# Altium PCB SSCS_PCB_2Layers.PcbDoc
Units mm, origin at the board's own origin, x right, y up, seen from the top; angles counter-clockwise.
Board outline 50.93 x 54.61 mm, 2 copper layers (Top Layer, Bottom Layer); 15 components, 35 nets, 400 pads, 22 vias.
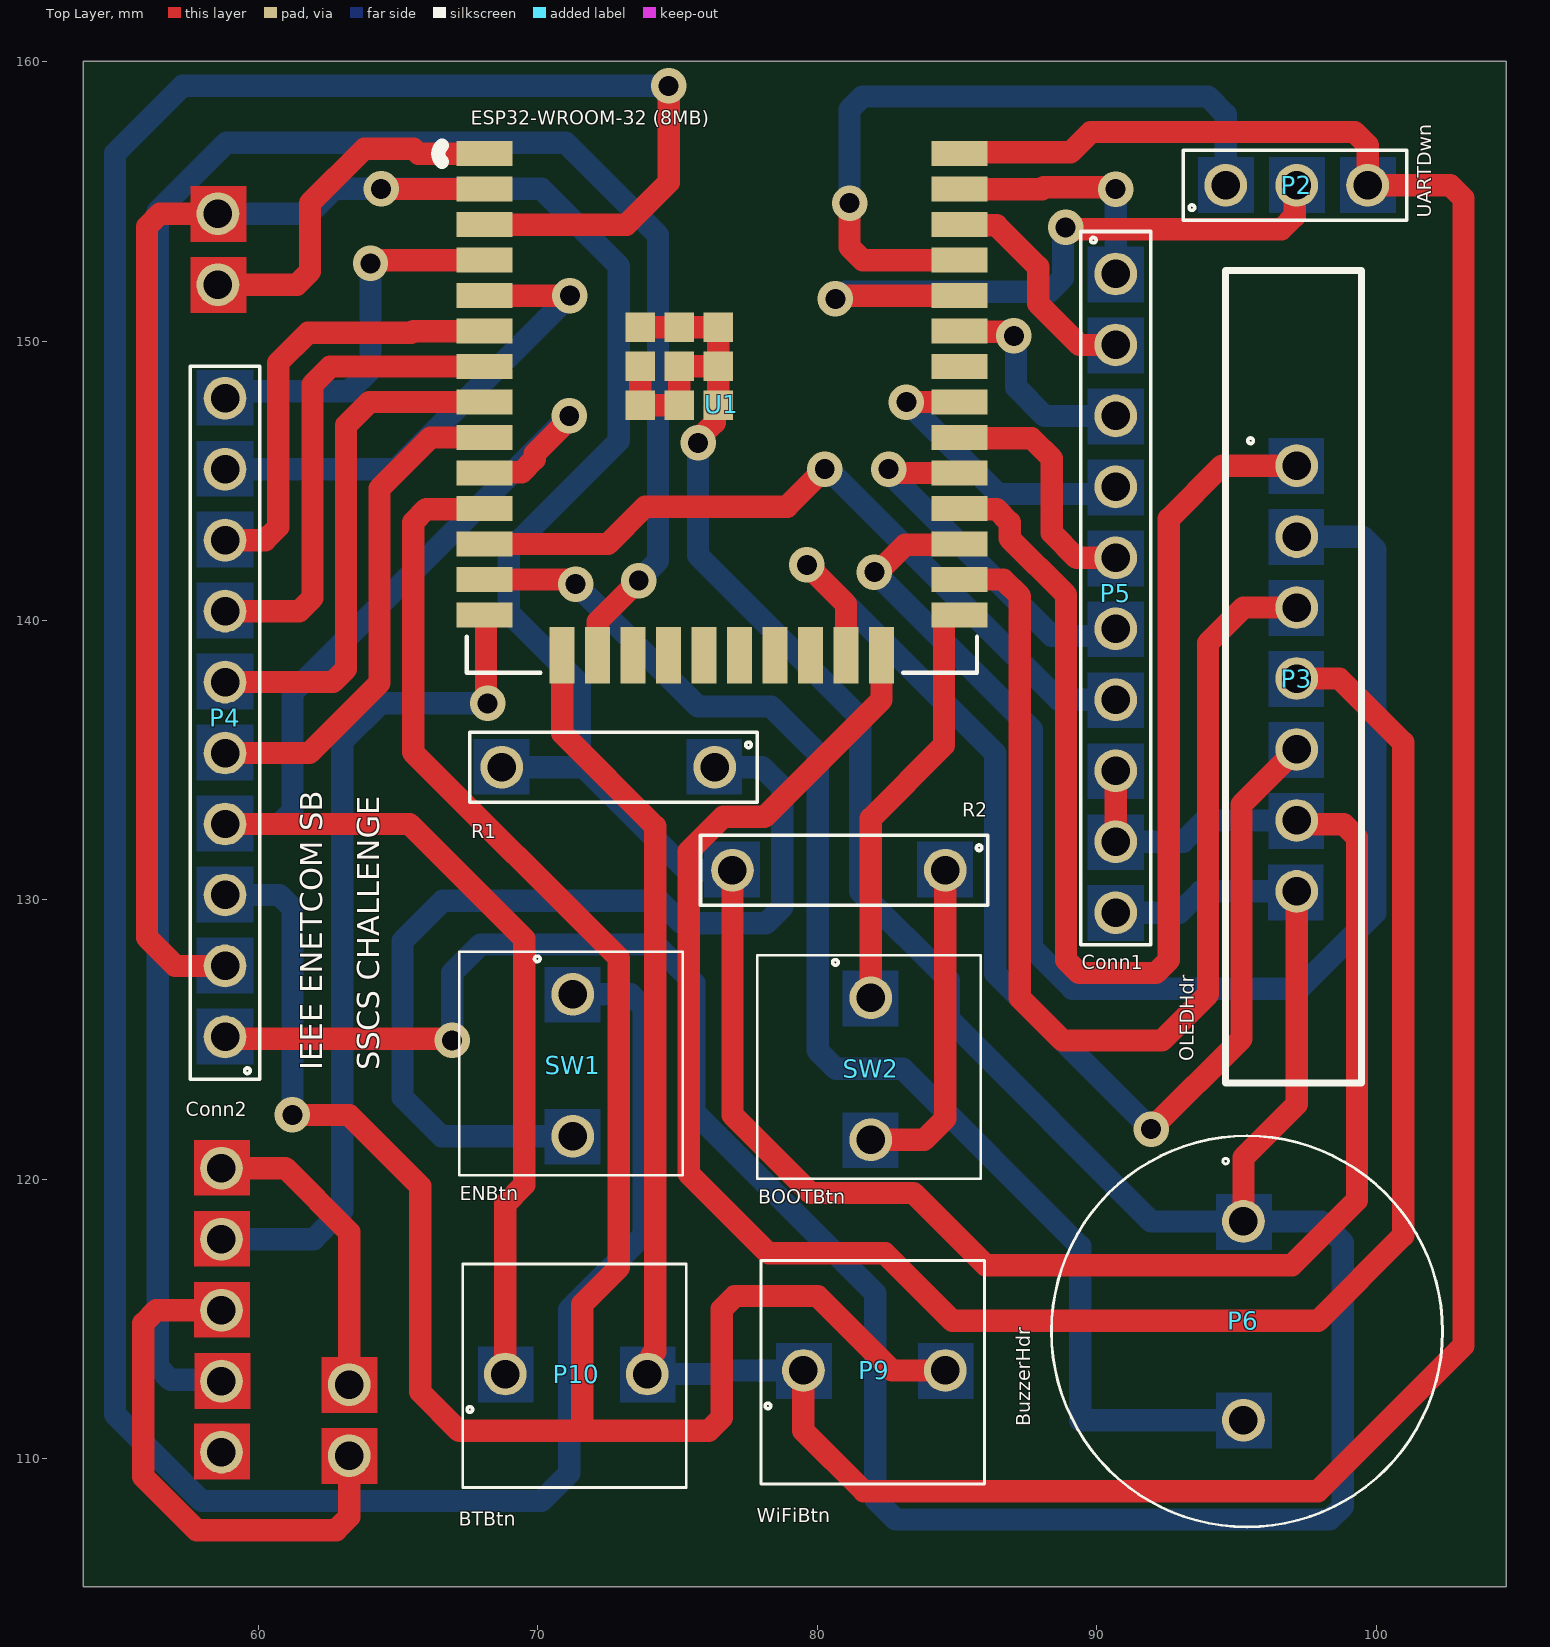
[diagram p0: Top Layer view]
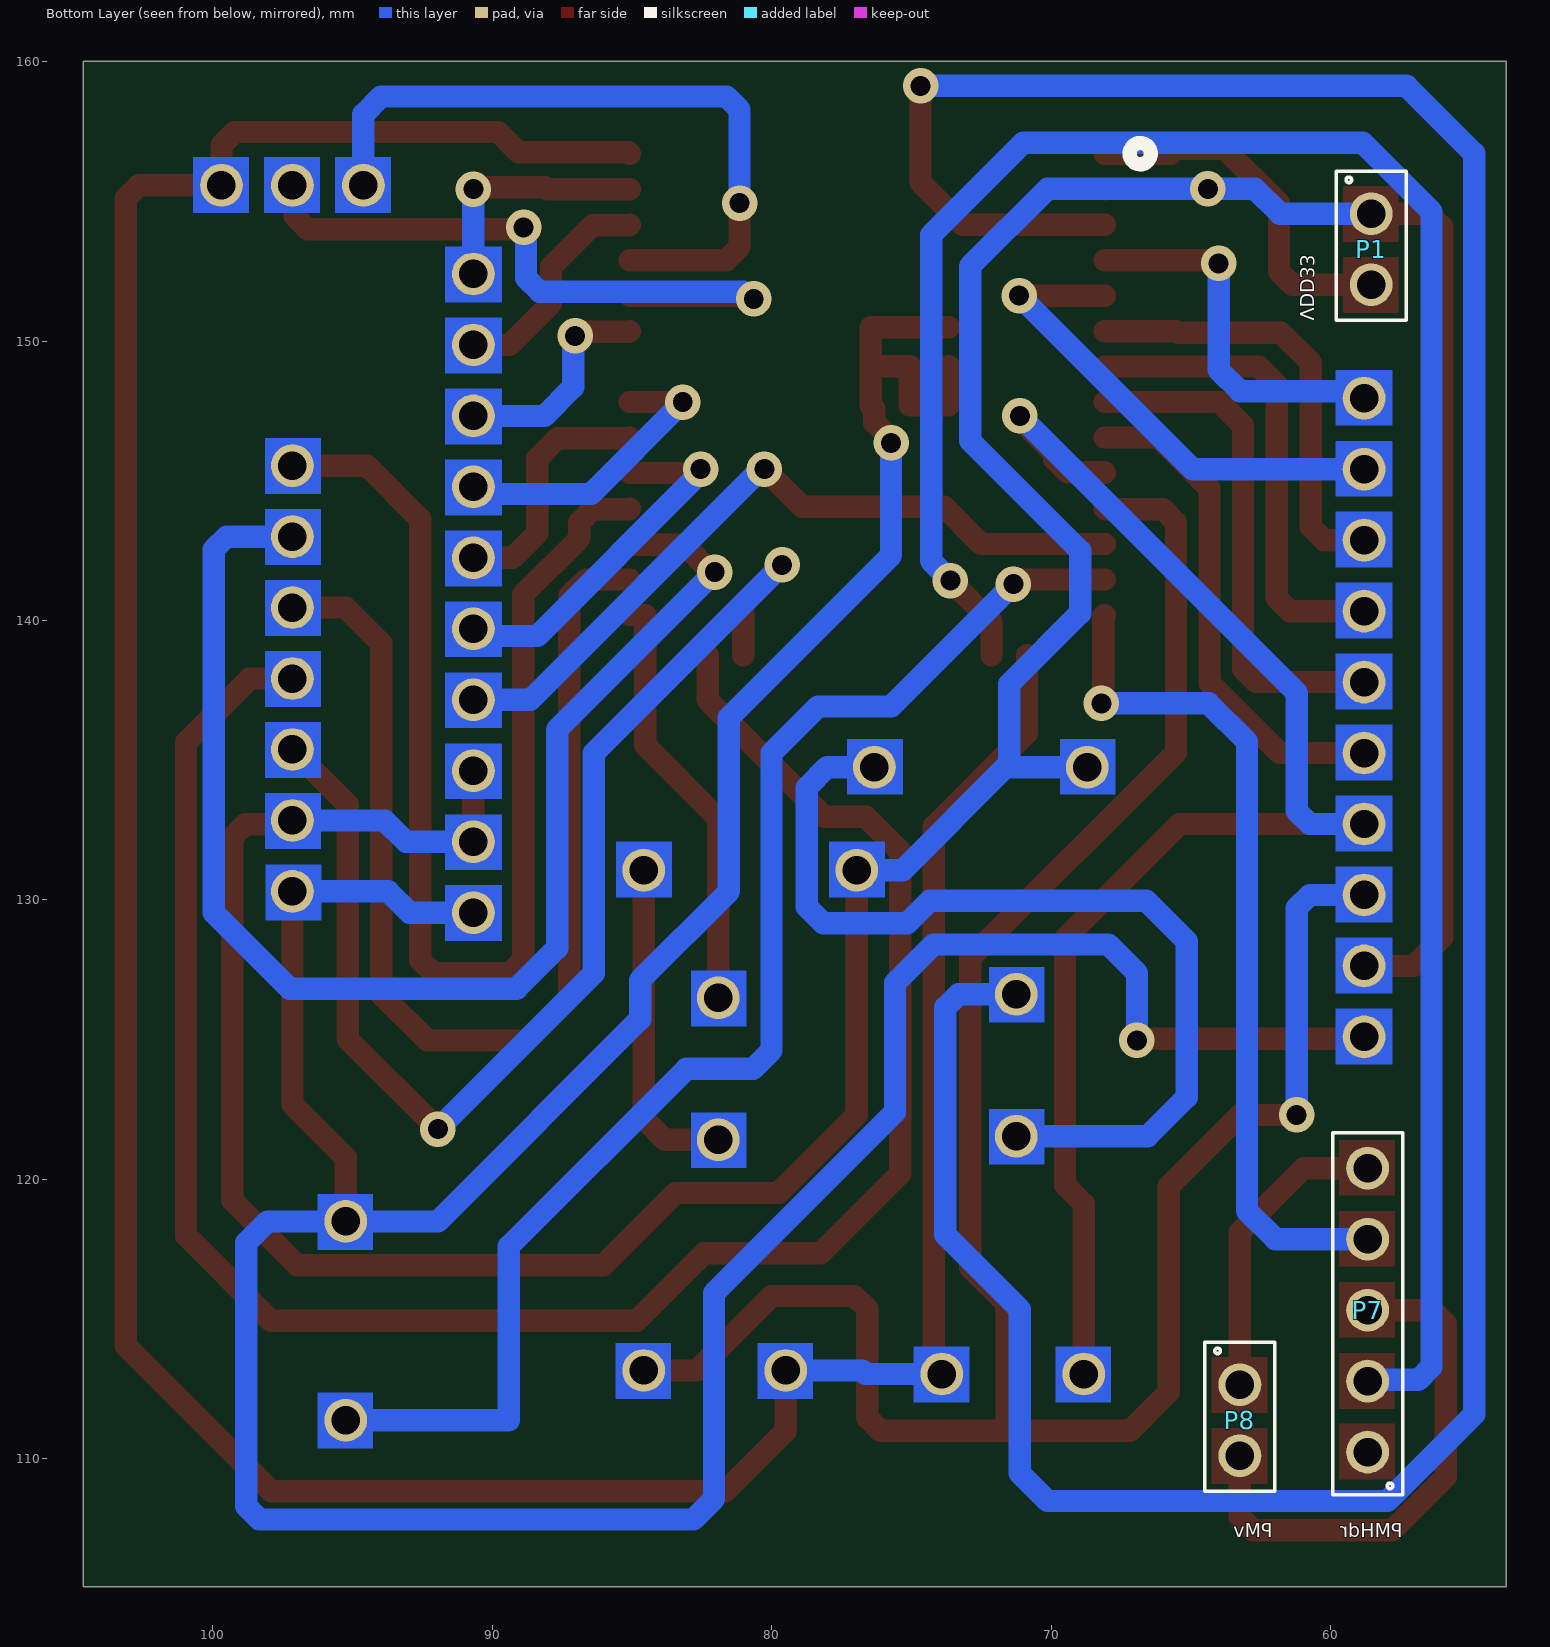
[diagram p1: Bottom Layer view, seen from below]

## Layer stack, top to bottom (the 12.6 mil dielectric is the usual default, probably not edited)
Top Solder: solder mask 0.0102, Solder Resist, Dk 3.5
Top Layer: signal copper 0.0356
Dielectric 1: dielectric 0.32, FR-4, Dk 4.8
Bottom Layer: signal copper 0.0356
Bottom Solder: solder mask 0.0102, Solder Resist, Dk 3.5

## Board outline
53.721,105.41 104.648,105.41 104.648,160.02 53.721,160.02

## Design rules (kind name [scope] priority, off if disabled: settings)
Clearance [All] p1: gap=0.4 ignorepadtopadclearanceinfootprint=FALSE
PolygonConnect [All] p1: connectstyle=Relief reliefconductorwidth=0.254 reliefentries=4 polygonreliefangle="90 Angle" airgapwidth=0.254
RoutingVias [All] p1: holewidth=0.711 width=1.27 viastyle="Through Hole" minholewidth=0.711 minwidth=1.27 maxholewidth=0.711 maxwidth=1.27
SMDNeckDown [All] p1: percent=90.000
SolderMaskExpansion [All] p1: expansion=0.102 istentingtop=FALSE
Width [All] p1: maxlimit=1 minlimit=0.8 preferedwidth=0.8
30 further rules are at their usual default settings.

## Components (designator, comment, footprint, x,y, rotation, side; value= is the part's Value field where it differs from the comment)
P1 "VDD33" CONN2X2.54 58.547,145.669 r270 bottom
P2 "UARTDwn" CONN3X2.54 103.505,155.575 r0 top
P3 "OLEDHdr" CONN7X2.54 69.088,152.908 r270 top
P4 "Conn2" CONN10X2.54 58.801,133.985 r90 top
P5 "Conn1" CONN10X2.54 90.678,143.51 r270 top
P6 "BuzzerHdr" CONN2X2.54BUZZER 95.377,114.681 r270 top
P7 "PMHdr" CONN5X2.54 58.674,119.126 r90 bottom
P8 "PMv" CONN2X2.54 63.246,103.759 r270 bottom
P9 "WiFiBtn" SW 87.249,115.697 r0 top
P10 "BTBtn" SW 76.581,115.57 r0 top
R1 "RC1206FR-131RL" RES 67.437,134.747 r180 top
R2 "RC1206FR-131RL" RES 75.692,131.064 r180 top
SW1 "ENBtn" SW 73.787,118.872 r270 top
SW2 "BOOTBtn" SW 84.455,118.745 r270 top
U1 "ESP32-WROOM-32 (8MB)" "IC38_ESP32-WROOM-32 8MB_EXP" 76.581,151.003 r0 top

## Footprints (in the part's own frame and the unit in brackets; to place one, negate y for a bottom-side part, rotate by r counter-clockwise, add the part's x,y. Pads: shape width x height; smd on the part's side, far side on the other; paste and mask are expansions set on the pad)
CONN2X2.54 [mm]
  round 1.53 hole 1.02: 1(-8.89,0) 2(-6.35,0)
  Bottom Layer region: -9.874,0.984 -7.874,0.984 -7.874,-1.016 -9.874,-1.016
  Bottom Layer region: -7.334,0.984 -5.334,0.984 -5.334,-1.016 -7.334,-1.016
  silkscreen extent -10.41,-1.25 -5.08,1.25
CONN2X2.54BUZZER [mm]
  round 1.53 hole 1.02: 1(-3.81,-0.127) 2(3.302,-0.127)
  Bottom Layer region: -4.794,-1.111 -2.794,-1.111 -2.794,0.889 -4.794,0.889
  Bottom Layer region: 2.318,-1.111 4.318,-1.111 4.318,0.889 2.318,0.889
  silkscreen extent -6.87,-7 7.13,7
CONN3X2.54 [mm]
  round 1.53 hole 1.02: 1(-8.89,0) 2(-6.35,0) 3(-3.81,0)
  Bottom Layer region: -9.874,-0.984 -7.874,-0.984 -7.874,1.016 -9.874,1.016
  Bottom Layer region: -7.334,-0.984 -5.334,-0.984 -5.334,1.016 -7.334,1.016
  Bottom Layer region: -4.794,-0.984 -2.794,-0.984 -2.794,1.016 -4.794,1.016
  silkscreen extent -10.41,-1.25 -2.41,1.25
CONN5X2.54 [mm]
  round 1.53 hole 1.02: 1(-8.89,0) 2(-6.35,0) 3(-3.81,0) 4(-1.27,0) 5(1.27,0)
  Bottom Layer region: 0.286,1.016 2.286,1.016 2.286,-0.984 0.286,-0.984
  Bottom Layer region: -2.254,1.016 -0.254,1.016 -0.254,-0.984 -2.254,-0.984
  Bottom Layer region: -4.794,1.016 -2.794,1.016 -2.794,-0.984 -4.794,-0.984
  Bottom Layer region: -7.35,1.031 -5.35,1.031 -5.35,-0.969 -7.35,-0.969
  Bottom Layer region: -9.874,1.016 -7.874,1.016 -7.874,-0.984 -9.874,-0.984
  silkscreen extent -10.41,-1.25 2.54,1.25
CONN7X2.54 [mm]
  round 1.53 hole 1.02: 1(7.366,28.067) 2(9.906,28.067) 3(12.446,28.067) 4(14.986,28.067) 5(17.526,28.067) 6(20.066,28.067) 7(22.606,28.067)
  Bottom Layer region: 6.382,27.051 8.382,27.051 8.382,29.051 6.382,29.051
  Bottom Layer region: 8.922,27.051 10.922,27.051 10.922,29.051 8.922,29.051
  Bottom Layer region: 11.462,27.051 13.462,27.051 13.462,29.051 11.462,29.051
  Bottom Layer region: 14.002,27.051 16.002,27.051 16.002,29.051 14.002,29.051
  Bottom Layer region: 16.542,27.051 18.542,27.051 18.542,29.051 16.542,29.051
  Bottom Layer region: 19.082,27.051 21.082,27.051 21.082,29.051 19.082,29.051
  Bottom Layer region: 21.644,27.034 23.644,27.034 23.644,29.034 21.644,29.034
  silkscreen extent 0.38,25.53 29.46,30.38
CONN10X2.54 [mm]
  round 1.53 hole 1.02: 1(-8.89,0) 2(-6.35,0) 3(-3.81,0) 4(-1.27,0) 5(1.27,0) 6(3.81,0) 7(6.35,0) 8(8.89,0) 9(11.43,0) 10(13.97,0)
  Bottom Layer region: -9.874,-1.016 -7.874,-1.016 -7.874,1.016 -9.874,1.016
  Bottom Layer region: -7.334,-1.016 -5.334,-1.016 -5.334,1.016 -7.334,1.016
  Bottom Layer region: -4.794,-1.016 -2.794,-1.016 -2.794,1.016 -4.794,1.016
  Bottom Layer region: -2.254,-1.016 -0.254,-1.016 -0.254,1.016 -2.254,1.016
  Bottom Layer region: 0.286,-1.016 2.286,-1.016 2.286,1.016 0.286,1.016
  Bottom Layer region: 2.826,-1.016 4.826,-1.016 4.826,1.016 2.826,1.016
  Bottom Layer region: 5.366,-1.016 7.366,-1.016 7.366,1.016 5.366,1.016
  Bottom Layer region: 7.906,-1.016 9.906,-1.016 9.906,1.016 7.906,1.016
  Bottom Layer region: 10.446,-1.016 12.446,-1.016 12.446,1.016 10.446,1.016
  Bottom Layer region: 12.986,-1.016 14.986,-1.016 14.986,1.016 12.986,1.016
  silkscreen extent -10.41,-1.25 15.11,1.25
"IC38_ESP32-WROOM-32 8MB_EXP" [mil]
  rect 79x35 on Top Solder paste+0 mask+0: 1(-334.65,224.56) 1(-334.65,224.56) 1(-334.65,224.56) 1(-334.65,224.56) 1(-334.65,224.56) 1(-334.65,224.56) 2(-334.65,174.56) 2(-334.65,174.56) 2(-334.65,174.56) 2(-334.65,174.56) 2(-334.65,174.56) 2(-334.65,174.56) 3(-334.65,124.56) 3(-334.65,124.56) 3(-334.65,124.56) 3(-334.65,124.56) 3(-334.65,124.56) 3(-334.65,124.56) 4(-334.65,74.56) 4(-334.65,74.56) 4(-334.65,74.56) 4(-334.65,74.56) 4(-334.65,74.56) 4(-334.65,74.56) 5(-334.65,24.56) 5(-334.65,24.56) 5(-334.65,24.56) 5(-334.65,24.56) 5(-334.65,24.56) 5(-334.65,24.56) 6(-334.65,-25.44) 6(-334.65,-25.44) 6(-334.65,-25.44) 6(-334.65,-25.44) 6(-334.65,-25.44) 6(-334.65,-25.44) 7(-334.65,-75.44) 7(-334.65,-75.44) 7(-334.65,-75.44) 7(-334.65,-75.44) 7(-334.65,-75.44) 7(-334.65,-75.44) 8(-334.65,-125.44) 8(-334.65,-125.44) 8(-334.65,-125.44) 8(-334.65,-125.44) 8(-334.65,-125.44) 8(-334.65,-125.44) 9(-334.65,-175.44) 9(-334.65,-175.44) 9(-334.65,-175.44) 9(-334.65,-175.44) 9(-334.65,-175.44) 9(-334.65,-175.44) 10(-334.65,-225.44) 10(-334.65,-225.44) 10(-334.65,-225.44) 10(-334.65,-225.44) 10(-334.65,-225.44) 10(-334.65,-225.44) 11(-334.65,-275.44) 11(-334.65,-275.44) 11(-334.65,-275.44) 11(-334.65,-275.44) 11(-334.65,-275.44) 11(-334.65,-275.44) 12(-334.65,-325.44) 12(-334.65,-325.44) 12(-334.65,-325.44) 12(-334.65,-325.44) 12(-334.65,-325.44) 12(-334.65,-325.44) 13(-334.65,-375.44) 13(-334.65,-375.44) 13(-334.65,-375.44) 13(-334.65,-375.44) 13(-334.65,-375.44) 13(-334.65,-375.44) 14(-334.65,-425.44) 14(-334.65,-425.44) 14(-334.65,-425.44) 14(-334.65,-425.44) 14(-334.65,-425.44) 14(-334.65,-425.44) 25(334.65,-425.44) 25(334.65,-425.44) 25(334.65,-425.44) 25(334.65,-425.44) 25(334.65,-425.44) 25(334.65,-425.44) 26(334.65,-375.44) 26(334.65,-375.44) 26(334.65,-375.44) 26(334.65,-375.44) 26(334.65,-375.44) 26(334.65,-375.44) 27(334.65,-325.44) 27(334.65,-325.44) 27(334.65,-325.44) 27(334.65,-325.44) 27(334.65,-325.44) 27(334.65,-325.44) 28(334.65,-275.44) 28(334.65,-275.44) 28(334.65,-275.44) 28(334.65,-275.44) 28(334.65,-275.44) 28(334.65,-275.44) 29(334.65,-225.44) 29(334.65,-225.44) 29(334.65,-225.44) 29(334.65,-225.44) 29(334.65,-225.44) 29(334.65,-225.44) 30(334.65,-175.44) 30(334.65,-175.44) 30(334.65,-175.44) 30(334.65,-175.44) 30(334.65,-175.44) 30(334.65,-175.44) 31(334.65,-125.44) 31(334.65,-125.44) 31(334.65,-125.44) 31(334.65,-125.44) 31(334.65,-125.44) 31(334.65,-125.44) 32(334.65,-75.44) 32(334.65,-75.44) 32(334.65,-75.44) 32(334.65,-75.44) 32(334.65,-75.44) 32(334.65,-75.44) 33(334.65,-25.44) 33(334.65,-25.44) 33(334.65,-25.44) 33(334.65,-25.44) 33(334.65,-25.44) 33(334.65,-25.44) 34(334.65,24.56) 34(334.65,24.56) 34(334.65,24.56) 34(334.65,24.56) 34(334.65,24.56) 34(334.65,24.56) 35(334.65,74.56) 35(334.65,74.56) 35(334.65,74.56) 35(334.65,74.56) 35(334.65,74.56) 35(334.65,74.56) 36(334.65,124.56) 36(334.65,124.56) 36(334.65,124.56) 36(334.65,124.56) 36(334.65,124.56) 36(334.65,124.56) 37(334.65,174.56) 37(334.65,174.56) 37(334.65,174.56) 37(334.65,174.56) 37(334.65,174.56) 37(334.65,174.56) 38(334.65,224.56) 38(334.65,224.56) 38(334.65,224.56) 38(334.65,224.56) 38(334.65,224.56) 38(334.65,224.56)
  rect 79x35 smd paste+0 mask+0: 1(-334.65,224.56) 1(-334.65,224.56) 1(-334.65,224.56) 2(-334.65,174.56) 2(-334.65,174.56) 2(-334.65,174.56) 3(-334.65,124.56) 3(-334.65,124.56) 3(-334.65,124.56) 4(-334.65,74.56) 4(-334.65,74.56) 4(-334.65,74.56) 5(-334.65,24.56) 5(-334.65,24.56) 5(-334.65,24.56) 6(-334.65,-25.44) 6(-334.65,-25.44) 6(-334.65,-25.44) 7(-334.65,-75.44) 7(-334.65,-75.44) 7(-334.65,-75.44) 8(-334.65,-125.44) 8(-334.65,-125.44) 8(-334.65,-125.44) 9(-334.65,-175.44) 9(-334.65,-175.44) 9(-334.65,-175.44) 10(-334.65,-225.44) 10(-334.65,-225.44) 10(-334.65,-225.44) 11(-334.65,-275.44) 11(-334.65,-275.44) 11(-334.65,-275.44) 12(-334.65,-325.44) 12(-334.65,-325.44) 12(-334.65,-325.44) 13(-334.65,-375.44) 13(-334.65,-375.44) 13(-334.65,-375.44) 14(-334.65,-425.44) 14(-334.65,-425.44) 14(-334.65,-425.44) 25(334.65,-425.44) 25(334.65,-425.44) 25(334.65,-425.44) 26(334.65,-375.44) 26(334.65,-375.44) 26(334.65,-375.44) 27(334.65,-325.44) 27(334.65,-325.44) 27(334.65,-325.44) 28(334.65,-275.44) 28(334.65,-275.44) 28(334.65,-275.44) 29(334.65,-225.44) 29(334.65,-225.44) 29(334.65,-225.44) 30(334.65,-175.44) 30(334.65,-175.44) 30(334.65,-175.44) 31(334.65,-125.44) 31(334.65,-125.44) 31(334.65,-125.44) 32(334.65,-75.44) 32(334.65,-75.44) 32(334.65,-75.44) 33(334.65,-25.44) 33(334.65,-25.44) 33(334.65,-25.44) 34(334.65,24.56) 34(334.65,24.56) 34(334.65,24.56) 35(334.65,74.56) 35(334.65,74.56) 35(334.65,74.56) 36(334.65,124.56) 36(334.65,124.56) 36(334.65,124.56) 37(334.65,174.56) 37(334.65,174.56) 37(334.65,174.56) 38(334.65,224.56) 38(334.65,224.56) 38(334.65,224.56)
  rect 35x79 on Top Paste paste-39.5 mask-39.5: 15(-225,-482.19) 15(-225,-482.19) 16(-175,-482.19) 16(-175,-482.19) 17(-125,-482.19) 17(-125,-482.19) 18(-75,-482.19) 18(-75,-482.19) 19(-25,-482.19) 19(-25,-482.19) 20(25,-482.19) 20(25,-482.19) 21(75,-482.19) 21(75,-482.19) 22(125,-482.19) 22(125,-482.19) 23(175,-482.19) 23(175,-482.19) 24(225,-482.19) 24(225,-482.19)
  rect 35x79 on Top Solder paste-39.5 mask-39.5: 15(-225,-482.19) 15(-225,-482.19) 16(-175,-482.19) 16(-175,-482.19) 17(-125,-482.19) 17(-125,-482.19) 18(-75,-482.19) 18(-75,-482.19) 19(-25,-482.19) 19(-25,-482.19) 20(25,-482.19) 20(25,-482.19) 21(75,-482.19) 21(75,-482.19) 22(125,-482.19) 22(125,-482.19) 23(175,-482.19) 23(175,-482.19) 24(225,-482.19) 24(225,-482.19)
  rect 35x79 smd paste-39.5 mask-39.5: 15(-225,-482.19) 16(-175,-482.19) 17(-125,-482.19) 18(-75,-482.19) 19(-25,-482.19) 20(25,-482.19) 21(75,-482.19) 22(125,-482.19) 23(175,-482.19) 24(225,-482.19)
  rect 41.34x41.34 on Top Paste paste-26 mask-26: 39(-115,-20) 39(-115,-20) 40(-60,-20) 40(-60,-20) 41(-5,-20) 41(-5,-20) 42(-115,-75) 42(-115,-75) 43(-60,-75) 43(-60,-75) 44(-5,-75) 44(-5,-75) 45(-115,-130) 45(-115,-130) 46(-60,-130) 46(-60,-130) 47(-5,-130) 47(-5,-130)
  rect 41.34x41.34 on Top Solder paste-26 mask-26: 39(-115,-20) 39(-115,-20) 40(-60,-20) 40(-60,-20) 41(-5,-20) 41(-5,-20) 42(-115,-75) 42(-115,-75) 43(-60,-75) 43(-60,-75) 44(-5,-75) 44(-5,-75) 45(-115,-130) 45(-115,-130) 46(-60,-130) 46(-60,-130) 47(-5,-130) 47(-5,-130)
  rect 41.34x41.34 smd paste-26 mask-26: 39(-115,-20) 40(-60,-20) 41(-5,-20) 42(-115,-75) 43(-60,-75) 44(-5,-75) 45(-115,-130) 46(-60,-130) 47(-5,-130)
  silkscreen extent -400,-507 360,236, body extent -350,-482 359,522, height 126
RES [mm]
  round 1.53 hole 1.02: 1(-8.89,0) 2(-1.27,0)
  Bottom Layer region: -2.254,-1.016 -0.254,-1.016 -0.254,0.984 -2.254,0.984
  Bottom Layer region: -9.874,-1.016 -7.874,-1.016 -7.874,0.984 -9.874,0.984
  silkscreen extent -10.41,-1.25 -0.13,1.25
SW [mm]
  round 1.53 hole 1.02: 1(-7.747,-2.54) 2(-2.667,-2.54)
  Bottom Layer region: -8.731,-3.556 -6.731,-3.556 -6.731,-1.556 -8.731,-1.556
  Bottom Layer region: -3.651,-3.556 -1.651,-3.556 -1.651,-1.556 -3.651,-1.556
  silkscreen extent -9.27,-6.6 -1.27,1.4

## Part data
P1 P6 P8 P9 P10: library part MHDR1X2, "Header, 2-Pin"
P2: library part MHDR1X3, "Header, 3-Pin"
P3: library part MHDR1X7, "Header, 7-Pin"
P4 P5: library part MHDR1X10, "Header, 10-Pin"
P7: library part MHDR1X5, "Header, 5-Pin"
R1 R2: "RC Series 1206 0.25 W 0 O Jumper Surface Mount Thick Film Chip Resistor", Package=None
SW1 SW2: library part 147873-1, "Switch Tactile OFF (ON) SPST Rectangular Button J-Bend 0.05A 24VDC 1.77N SMD T/R", Package=None
U1: library part "ESP32-WROOM-32 8MB", "No Description Available", Mfr_Name="Espressif Systems"

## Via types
v1: diameter 1.27, hole 0.711, Top Layer to Bottom Layer, 22 vias

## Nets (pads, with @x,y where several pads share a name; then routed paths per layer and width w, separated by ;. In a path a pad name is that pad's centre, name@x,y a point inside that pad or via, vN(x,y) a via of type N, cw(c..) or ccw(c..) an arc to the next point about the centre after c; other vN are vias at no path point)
BOOT: SW2.1 U1.25@85.081,140.197 | length 15.3
  Top Layer w0.8: SW2.1 81.915,132.918 84.531,135.534 84.531,140.197 U1.25@85.081,140.197
CS: P3.1 U1.28@85.081,144.007 | length 43.7
  Top Layer w0.8: U1.28@85.081,144.007 85.107,143.981 86.416,143.981 86.884,143.513 86.884,142.94 88.9,140.924 88.9,127.85 89.369,127.381 92.114,127.381 92.583,127.85 92.583,143.637 94.488,145.542 P3.1
D0: P3.5 U1.23@81.026,138.756 | length 44.9
  Top Layer w0.8: v1(79.629,141.986) 81.026,140.589 U1.23@81.026,138.756 ; v1(91.948,121.793) 95.18,125.025 95.18,133.407 P3.5
  Bottom Layer w0.8: v1(79.629,141.986) 86.366,135.249 86.366,127.375 v1(91.948,121.793)
D1: P3.4 U1.24@82.296,138.756 | length 73.7
  Top Layer w0.8: U1.24@82.296,138.756 82.296,137.16 78.105,132.969 76.632,132.969 75.397,131.734 75.397,120.207 78.256,117.348 82.423,117.348 84.836,114.935 97.917,114.935 100.965,117.983 100.965,135.636 98.679,137.922 P3.4
DC: P3.2 U1.27@85.081,142.737 | length 49.3
  Top Layer w0.8: v1(82.042,141.732) 82.169,141.732 83.148,142.711 85.055,142.711 U1.27@85.081,142.737
  Bottom Layer w0.8: v1(82.042,141.732) 87.681,136.093 87.681,128.27 89.129,126.822 97.257,126.822 99.974,129.54 99.974,142.533 99.506,143.002 P3.2
EN: SW1.1 U1.3@68.081,154.167 | length 115.1
  Top Layer w0.8: U1.3@68.081,154.167 73.169,154.167 74.676,155.674 v1(74.676,159.131)
  Bottom Layer w0.8: SW1.1 73.318,126.619 73.787,126.15 73.787,118.008 71.12,115.341 71.12,109.474 70.129,108.483 57.963,108.483 54.864,111.582 54.864,156.718 57.277,159.131 v1(74.676,159.131)
GND0: P3.7 P4.1 P5.10 P6.1 U1.39@73.66,150.495 U1.40@75.057,150.495 U1.41@76.454,150.495 U1.42@73.66,149.098 U1.43@75.057,149.098 U1.44@76.454,149.098 U1.45@73.66,147.701 U1.46@75.057,147.701 U1.47@76.454,147.701 | length 142
  Top Layer w0.8: P4.1 58.864,125.031 66.865,125.031 v1(66.929,124.968) ; U1.42@73.66,149.098 73.66,147.701 75.057,147.701 75.057,149.098 U1.44@76.454,149.098 ; U1.39@73.66,150.495 75.057,150.495 76.454,150.495 U1.44@76.454,149.098 ; v1(75.73,146.355) 75.73,146.482 76.329,147.081 76.329,147.576 76.454,147.701 U1.44@76.454,149.098 ; P6.1 95.25,120.777 97.155,122.682 P3.7
  Bottom Layer w0.8: v1(66.929,124.968) 66.929,127.381 67.951,128.403 74.213,128.403 75.59,127.025 75.59,122.403 82.067,115.926 82.067,108.56 82.804,107.823 98.337,107.823 98.806,108.292 98.806,117.729 98.044,118.491 P6.1 91.948,118.491 84.709,125.73 84.709,127.127 81.534,130.302 81.534,136.525 75.73,142.329 v1(75.73,146.355) ; P5.10 92.964,129.54 93.726,130.302 P3.7
GND1: P1.2 U1.1@68.081,156.707 | length 13.1
  Top Layer w0.8: P1.2 61.376,152.019 61.844,152.488 61.844,154.933 63.795,156.883 65.548,156.883 65.724,156.707 U1.1@68.081,156.707
GND2: P2.3 P9.1 P10.2 U1.15@70.866,138.756 U1.38@85.081,156.707 | length 122.9
  Top Layer w0.8: U1.15@70.866,138.756 70.866,135.966 74.197,132.635 74.197,113.829 74.054,113.686 74.054,113.17 P10.2 ; P9.1 79.502,110.998 81.661,108.839 97.917,108.839 103.124,114.046 103.124,155.106 102.655,155.575 P2.3 99.695,157.011 99.226,157.48 89.789,157.48 89.06,156.751 85.125,156.751 U1.38@85.081,156.707
  Bottom Layer w0.8: P10.2 76.632,113.03 76.759,113.157 P9.1
GND_1: P7.5 P8.1 | length 11
  Top Layer w0.8: P7.5 60.96,120.396 63.246,118.11 P8.1
IO5: P5.6 U1.29@85.081,145.277 | length 13.4
  Top Layer w0.8: v1(82.55,145.415) 82.677,145.415 82.815,145.277 U1.29@85.081,145.277
  Bottom Layer w0.8: v1(82.55,145.415) 82.55,145.288 88.392,139.446 89.908,139.446 90.022,139.56 90.538,139.56 P5.6
IO12: P7.4 U1.14@68.081,140.197 | length 30.5
  Top Layer w0.8: U1.14@68.081,140.197 68.095,140.197 68.14,140.152 68.14,137.092 v1(68.199,137.033)
  Bottom Layer w0.8: P7.4 61.976,117.856 62.992,118.872 62.992,135.661 64.364,137.033 v1(68.199,137.033)
IO13: P7.2 U1.16@72.136,138.756 | length 80.1
  Top Layer w0.8: U1.16@72.136,138.756 72.136,139.954 v1(73.609,141.427)
  Bottom Layer w0.8: P7.2 58.627,112.823 56.857,112.823 56.388,113.292 56.388,154.635 58.852,157.099 70.993,157.099 74.295,153.797 74.295,142.131 73.609,141.445 v1(73.609,141.427)
IO14: P6.2 U1.13@68.081,141.467 | length 49.5
  Top Layer w0.8: U1.13@68.081,141.467 71.056,141.467 71.221,141.302 v1(71.349,141.302)
  Bottom Layer w0.8: v1(71.349,141.302) 75.73,136.921 78.344,136.921 80.01,135.255 80.01,124.612 80.67,123.952 83.058,123.952 89.408,117.602 89.408,111.379 P6.2
IO18: P5.5 U1.30@85.081,146.547 | length 8.9
  Top Layer w0.8: U1.30@85.081,146.547 85.106,146.521 87.667,146.521 88.392,145.796 88.392,143.129 89.281,142.24 P5.5
IO19: P5.4 U1.31@85.081,147.817 | length 10.9
  Top Layer w0.8: v1(83.185,147.817) U1.31@85.081,147.817
  Bottom Layer w0.8: v1(83.185,147.817) 86.476,144.526 89.908,144.526 90.022,144.64 90.538,144.64 P5.4
IO21: P5.3 U1.33@85.081,150.357 | length 7.9
  Top Layer w0.8: U1.33@85.081,150.357 85.107,150.331 86.76,150.331 86.908,150.183 v1(87.036,150.183)
  Bottom Layer w0.8: v1(87.036,150.183) 87.11,150.108 87.11,148.348 88.138,147.32 P5.3
IO22: P5.2 U1.36@85.081,154.167 | length 8.1
  Top Layer w0.8: U1.36@85.081,154.167 85.107,154.141 86.416,154.141 87.902,152.655 87.902,151.346 89.388,149.86 P5.2
IO23: P5.1 U1.37@85.081,155.437 | length 8.7
  Top Layer w0.8: U1.37@85.081,155.437 88.041,155.437 88.104,155.5 90.614,155.5 v1(90.678,155.437)
  Bottom Layer w0.8: P5.1 v1(90.678,155.437)
IO25: P4.4 P10.1 U1.10@68.081,145.277 | length 53.2
  Top Layer w0.8: P4.4 65.405,132.715 69.507,128.613 69.507,119.795 68.834,119.122 P10.1 ; U1.10@68.081,145.277 68.106,145.302 69.416,145.302 69.884,145.771 69.884,145.961 71.12,147.196 v1(71.12,147.32)
  Bottom Layer w0.8: P4.4 60.745,132.715 61.214,133.184 61.214,137.414 v1(71.12,147.32)
IO26: P4.3 P9.2 U1.11@68.081,144.007 | length 86.6
  Top Layer w0.8: v1(61.214,122.301) 63.246,122.301 65.786,119.761 65.786,112.395 67.183,110.998 71.589,110.998 ; U1.11@68.081,144.007 68.055,143.981 66.001,143.981 65.532,143.513 65.532,135.28 72.898,127.914 72.898,116.84 71.589,115.531 71.589,110.998 ; P9.2 82.677,113.157 80.01,115.824 77.05,115.824 76.581,115.355 76.581,111.467 76.112,110.998 71.589,110.998
  Bottom Layer w0.8: P4.3 60.745,130.175 61.214,129.706 v1(61.214,122.301)
IO27: P5.7 U1.12@68.081,142.737 | length 27.1
  Top Layer w0.8: U1.12@68.081,142.737 72.506,142.737 73.841,144.072 78.921,144.072 v1(80.264,145.415)
  Bottom Layer w0.8: v1(80.264,145.415) 80.388,145.415 88.643,137.16 P5.7
IO32: P4.6 U1.8@68.081,147.817 | length 18.5
  Top Layer w0.8: P4.6 62.663,137.795 63.132,138.264 63.132,146.98 63.969,147.817 U1.8@68.081,147.817
IO33: P4.5 U1.9@68.081,146.547 | length 18
  Top Layer w0.8: P4.5 61.82,135.255 64.332,137.767 64.332,144.723 66.156,146.547 U1.9@68.081,146.547
IO34: P4.8 U1.6@68.081,150.357 | length 15.8
  Top Layer w0.8: P4.8 60.237,142.875 60.706,143.344 60.706,149.225 61.773,150.292 65.47,150.292 65.535,150.357 U1.6@68.081,150.357
IO35: P4.7 U1.7@68.081,149.087 | length 17.4
  Top Layer w0.8: P4.7 61.463,140.335 61.932,140.804 61.932,148.447 62.572,149.087 U1.7@68.081,149.087
NetR1_1: R1.1 SW1.2 | length 34
  Bottom Layer w0.8: SW1.2 66.548,121.539 65.151,122.936 65.151,128.524 66.591,129.964 74.349,129.964 75.154,129.159 78.156,129.159 78.746,129.749 78.746,134.018 78.017,134.747 R1.1
NetR2_1: R2.1 SW2.2 | length 11.9
  Top Layer w0.8: SW2.2 83.82,121.412 84.582,122.174 R2.1
RES: P3.3 U1.26@85.081,141.467 | length 41.1
  Top Layer w0.8: U1.26@85.081,141.467 86.651,141.467 87.249,140.868 87.249,126.492 88.773,124.968 92.329,124.968 93.98,126.619 93.98,139.192 95.25,140.462 P3.3
RXD0: P2.2 U1.34@85.081,151.627 | length 24.3
  Top Layer w0.8: v1(80.645,151.511) 80.772,151.511 80.888,151.627 U1.34@85.081,151.627 ; v1(88.883,154.065) 88.947,154.002 96.612,154.002 97.081,154.47 97.081,155.501 P2.2
  Bottom Layer w0.8: v1(80.645,151.511) 80.772,151.511 81.026,151.765 88.304,151.765 88.794,152.254 88.794,153.976 v1(88.883,154.065)
SENSOR_VN: P4.9 U1.5@68.081,151.627 | length 18
  Top Layer w0.8: U1.5@68.081,151.627 v1(71.145,151.627)
  Bottom Layer w0.8: P4.9 64.934,145.415 v1(71.145,151.627)
SENSOR_VP: P4.10 U1.4@68.081,152.897 | length 13.6
  Top Layer w0.8: v1(64.008,152.781) 64.135,152.781 64.251,152.897 U1.4@68.081,152.897
  Bottom Layer w0.8: P4.10 58.941,148.095 59.457,148.095 59.571,148.209 63.246,148.209 64.008,148.971 v1(64.008,152.781)
TXD0: P2.1 U1.35@85.081,152.897 | length 25.5
  Top Layer w0.8: v1(81.153,154.94) 81.153,153.365 81.622,152.897 U1.35@85.081,152.897
  Bottom Layer w0.8: v1(81.153,154.94) 81.153,158.281 81.622,158.75 93.98,158.75 94.615,158.115 P2.1
VDD33: P1.1 P3.6 P4.2 P5.8 P5.9 R1.2 R2.2 U1.2@68.081,155.437 | length 140.4
  Top Layer w0.8: P1.1 56.476,154.559 56.007,154.09 56.007,128.651 57.023,127.635 P4.2 ; v1(64.389,155.448) 64.395,155.442 68.075,155.442 U1.2@68.081,155.437 ; R2.2 76.962,122.301 79.756,119.507 83.439,119.507 86.02,116.926 96.987,116.926 99.314,119.253 99.314,132.234 98.845,132.702 97.295,132.702 P3.6 ; P5.9 P5.8
  Bottom Layer w0.8: P1.1 61.817,154.559 62.706,155.448 v1(64.389,155.448) 70.129,155.448 72.898,152.679 72.898,146.431 68.961,142.494 68.961,140.259 71.501,137.719 71.501,134.747 ; R1.2 71.501,134.747 ; R2.2 75.311,131.064 71.628,134.747 71.501,134.747 ; P5.9 93.091,132.08 93.853,132.842 P3.6
VDD33_1: P7.3 P8.2 | length 19
  Top Layer w0.8: P7.3 56.349,115.316 55.88,114.847 55.88,109.347 57.785,107.442 62.777,107.442 63.246,107.911 P8.2
pads on no net: P7.1 U1.1@68.081,156.707 U1.2@68.081,155.437 U1.3@68.081,154.167 U1.4@68.081,152.897 U1.5@68.081,151.627 U1.6@68.081,150.357 U1.7@68.081,149.087 U1.8@68.081,147.817 U1.9@68.081,146.547 U1.10@68.081,145.277 U1.11@68.081,144.007 U1.12@68.081,142.737 U1.13@68.081,141.467 U1.14@68.081,140.197 U1.15@70.866,138.756 U1.16@72.136,138.756 U1.17 U1.18 U1.19 U1.20 U1.21 U1.22 U1.23@81.026,138.756 U1.24@82.296,138.756 U1.25@85.081,140.197 U1.26@85.081,141.467 U1.27@85.081,142.737 U1.28@85.081,144.007 U1.29@85.081,145.277 U1.30@85.081,146.547 U1.31@85.081,147.817 U1.32 U1.33@85.081,150.357 U1.34@85.081,151.627 U1.35@85.081,152.897 U1.36@85.081,154.167 U1.37@85.081,155.437 U1.38@85.081,156.707 U1.39@73.66,150.495 U1.40@75.057,150.495 U1.41@76.454,150.495 U1.42@73.66,149.098 U1.43@75.057,149.098 U1.44@76.454,149.098 U1.45@73.66,147.701 U1.46@75.057,147.701 U1.47@76.454,147.701

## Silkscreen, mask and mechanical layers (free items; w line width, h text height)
Top Overlay:
  text "IEEE ENETCOM SB" at 62.284,123.898 h0.8 r90
  text "SSCS CHALLENGE" at 64.316,123.898 h0.8 r90
Board Shape:
  the board outline again, w1.2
